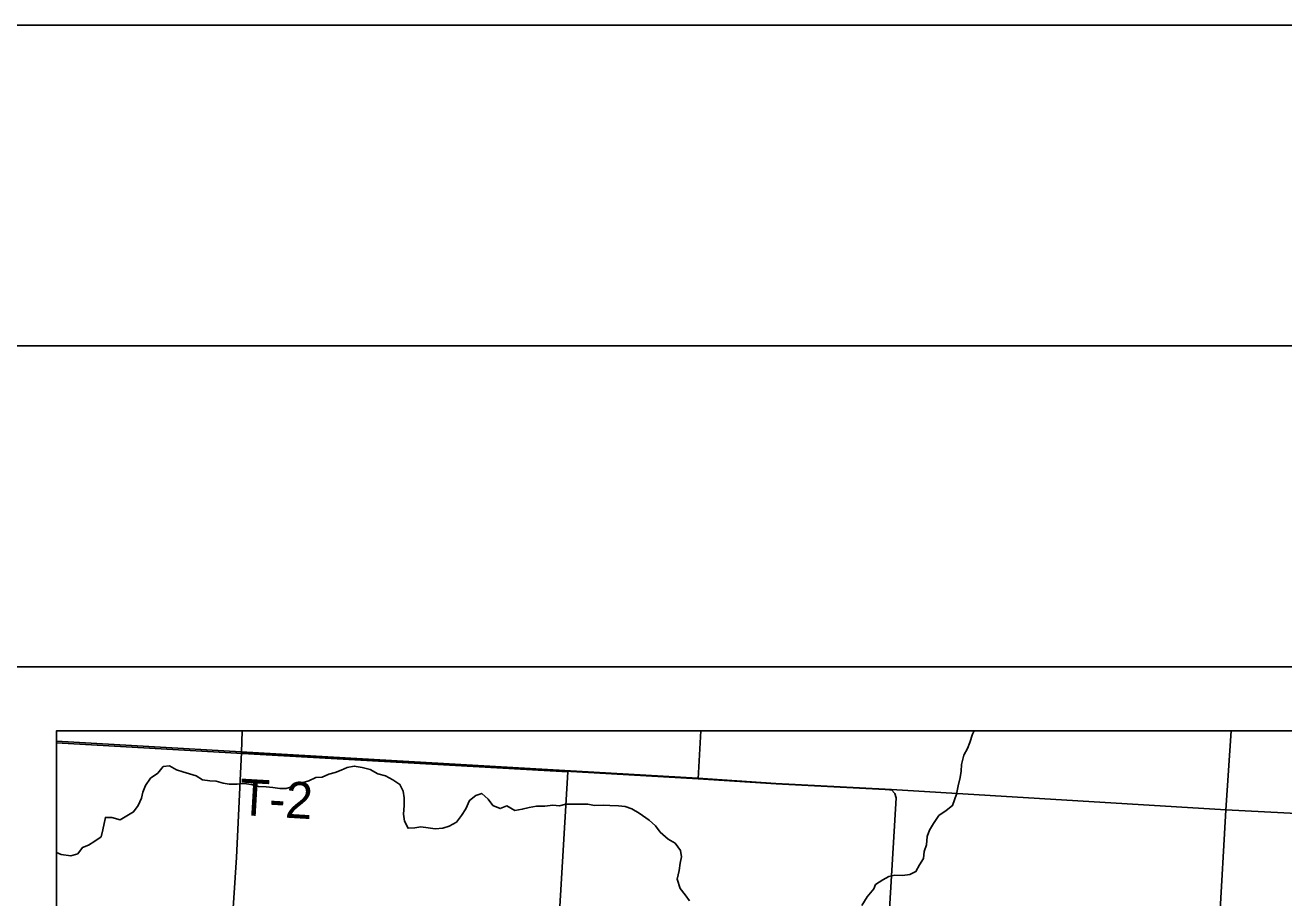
# Model space of a CAD drawing. Extents: x 0 to 91.3, y -0.7 to 22.
# Drawn here: x 2.051 to 4.012, y 20.64 to 22 of the extents above; entities that cross this region are included whole.
import ezdxf

# ---------------------------------------------------------------- set-up
doc = ezdxf.new("R2010")
doc.units = 0
for name, color, linetype in [('GM_X_Corporation', 7, 'Continuous'), ('GM_X_County_Road', 7, 'Continuous'), ('GM_X_Minor_River', 7, 'Continuous'), ('GM_X_State_Route', 7, 'Continuous'), ('GM_X_Township_Road', 7, 'Continuous'), ('GM_X_Township_Road_Text', 7, 'Continuous'), ('SH_Border', 7, 'Continuous'), ('SH_Cut_Line', 7, 'Continuous'), ('SH_Data', 7, 'Continuous')]:
    doc.layers.add(name, color=color, linetype=linetype)

msp = doc.modelspace()

# ---------------------------------------------------------------- linework, layer by layer
at = {"layer": 'GM_X_Corporation'}
for points in [[(4.9555, 20.9), (2.1, 20.9), (2.1, 20.8844), (2.3878, 20.8673), (3.0994, 20.8263), (3.2209, 20.8181), (3.3908, 20.8093), (3.4006, 20.8086), (3.9216, 20.777), (4.9448, 20.7239)], [(4.9555, 20.9), (2.1, 20.9), (2.1, 20.8844), (2.3878, 20.8673), (3.0994, 20.8263), (3.2209, 20.8181), (3.3908, 20.8093), (3.4006, 20.8086), (3.9216, 20.777), (4.9448, 20.7239)], [(2.1, 20.8816), (2.1, 19.8366), (2.8346, 19.7864), (2.8964, 20.8363), (2.3899, 20.8648)]]:
    msp.add_lwpolyline(points, close=True, dxfattribs=at)
for points in [[(4.7833, 18.1361), (4.8242, 18.6326), (4.8251, 18.6439), (4.8263, 18.646), (4.8271, 18.6491), (4.8277, 18.656), (4.8336, 18.7529), (4.834, 18.7568), (4.8352, 18.7619), (4.9205, 20.3667), (4.9376, 20.6305), (4.9448, 20.7239), (3.9216, 20.777), (3.4006, 20.8086), (3.3908, 20.8093), (3.2209, 20.8181), (3.0994, 20.8263), (2.3878, 20.8673), (2.1, 20.8844), (2.1, 14.1)], [(4.7833, 18.1361), (4.8242, 18.6326), (4.8251, 18.6439), (4.8263, 18.646), (4.8271, 18.6491), (4.8277, 18.656), (4.8336, 18.7529), (4.834, 18.7568), (4.8352, 18.7619), (4.9205, 20.3667), (4.9376, 20.6305), (4.9448, 20.7239), (3.9216, 20.777), (3.4006, 20.8086), (3.3908, 20.8093), (3.2209, 20.8181), (3.0994, 20.8263), (2.3878, 20.8673), (2.1, 20.8844), (2.1, 15.7138)]]:
    msp.add_lwpolyline(points, dxfattribs=at)
at = {"layer": 'GM_X_County_Road'}
msp.add_lwpolyline([(3.8606, 19.7255), (3.8807, 20.1515), (3.9073, 20.5159), (3.9118, 20.603), (3.9219, 20.7764)], dxfattribs=at)
at = {"layer": 'GM_X_Minor_River'}
for points in [[(3.502, 20.8014), (3.5048, 20.8146), (3.5078, 20.8275), (3.5093, 20.8374), (3.51, 20.848), (3.5133, 20.8621), (3.5193, 20.8727), (3.5231, 20.8822), (3.5272, 20.8952), (3.5297, 20.9)], [(2.1, 20.7104), (2.1072, 20.7075), (2.1223, 20.7054), (2.1333, 20.7084), (2.1406, 20.7182), (2.1501, 20.7222), (2.16, 20.7282), (2.1695, 20.7353), (2.1723, 20.746), (2.1742, 20.7558), (2.1762, 20.7653), (2.1861, 20.7652), (2.1993, 20.7613), (2.2099, 20.768), (2.2202, 20.774), (2.2271, 20.7838), (2.2325, 20.7951), (2.2345, 20.8046), (2.2387, 20.8152), (2.2468, 20.8265), (2.2578, 20.8343), (2.2663, 20.8449), (2.2761, 20.8456), (2.287, 20.8397), (2.2968, 20.8366), (2.3074, 20.8331), (2.3179, 20.8299), (2.3277, 20.8241), (2.3391, 20.8221), (2.3489, 20.822), (2.3595, 20.8189), (2.3693, 20.8172), (2.3818, 20.8171), (2.3924, 20.8181), (2.4033, 20.8165), (2.415, 20.8137), (2.4267, 20.8129), (2.4373, 20.812), (2.4479, 20.8104), (2.4577, 20.8103), (2.4703, 20.8139), (2.4805, 20.8188), (2.493, 20.8221), (2.5041, 20.8273), (2.5139, 20.8279), (2.5245, 20.8327), (2.534, 20.8353), (2.5435, 20.839), (2.553, 20.8431), (2.564, 20.8453), (2.5761, 20.8429), (2.5886, 20.8401), (2.6006, 20.8331), (2.6127, 20.8303), (2.624, 20.8237), (2.6352, 20.8168), (2.6401, 20.8061), (2.6419, 20.7958), (2.6418, 20.7837), (2.6405, 20.7704), (2.6423, 20.7594), (2.6479, 20.7483), (2.6585, 20.7489), (2.6679, 20.7504), (2.6789, 20.7491), (2.6902, 20.7475), (2.702, 20.7485), (2.7118, 20.7518), (2.7232, 20.7578), (2.7309, 20.7683), (2.7378, 20.7785), (2.7436, 20.7918), (2.7531, 20.7996), (2.7626, 20.8026), (2.7728, 20.7937), (2.7799, 20.7838), (2.7915, 20.7791), (2.8018, 20.7836), (2.8142, 20.7762), (2.8256, 20.778), (2.8366, 20.7809), (2.8476, 20.7827), (2.8608, 20.783), (2.8733, 20.7844), (2.8839, 20.7835), (2.8934, 20.7857), (2.9059, 20.7859), (2.9157, 20.7862)], [(2.9157, 20.7862), (2.9278, 20.7857), (2.9384, 20.7837), (2.9516, 20.7843), (2.9622, 20.7838), (2.9755, 20.7833), (2.986, 20.7821), (2.9966, 20.7789), (3.0079, 20.772), (3.0233, 20.7608), (3.0334, 20.752), (3.0405, 20.7424), (3.0529, 20.7316), (3.0638, 20.7251), (3.0721, 20.714), (3.0739, 20.7037), (3.0719, 20.6942), (3.0699, 20.6824), (3.0671, 20.6692), (3.0714, 20.6544)], [(3.502, 20.8014), (3.4961, 20.7838), (3.4858, 20.7763), (3.4748, 20.7684), (3.4663, 20.7559), (3.4598, 20.7454), (3.4563, 20.7355), (3.4554, 20.7226), (3.4519, 20.7124), (3.4507, 20.7014), (3.4446, 20.6916), (3.4388, 20.681), (3.4293, 20.6762), (3.4179, 20.6747), (3.4062, 20.6752), (3.3967, 20.6731), (3.3872, 20.6678), (3.3758, 20.6607), (3.3735, 20.6541)], [(3.5018, 20.8008), (3.5018, 20.8009)], [(3.0714, 20.6544), (3.0793, 20.6448), (3.0861, 20.6353)], [(3.3544, 20.628), (3.3632, 20.6413), (3.3735, 20.6541)]]:
    msp.add_lwpolyline(points, dxfattribs=at)
at = {"layer": 'GM_X_State_Route'}
msp.add_line((2.3881, 20.8667), (2.3891, 20.9), dxfattribs=at)
msp.add_lwpolyline([(2.3236, 19.8526), (2.354, 20.2835), (2.3719, 20.5693), (2.3803, 20.7028), (2.3881, 20.8667)], dxfattribs=at)
at = {"layer": 'GM_X_Township_Road'}
for p, q in [((3.0997, 20.8257), (3.104, 20.9)), ((3.9219, 20.7764), (3.93, 20.9))]:
    msp.add_line(p, q, dxfattribs=at)
for points in [[(2.3881, 20.8667), (3.0997, 20.8257), (3.2212, 20.8176), (3.391, 20.8088), (3.3975, 20.8083), (3.4008, 20.8081)], [(3.3467, 19.7553), (3.3647, 20.0567), (3.3715, 20.1817), (3.377, 20.2742), (3.4081, 20.7959), (3.4063, 20.8026), (3.4008, 20.8081)]]:
    msp.add_lwpolyline(points, dxfattribs=at)
at = {"layer": 'SH_Border'}
msp.add_lwpolyline([(1.5, 21.5), (33.5, 21.5), (33.5, 0.5), (1.5, 0.5)], close=True, dxfattribs=at)
at = {"layer": 'SH_Cut_Line'}
msp.add_lwpolyline([(0, 0), (34, 0), (34, 22), (0, 22)], close=True, dxfattribs=at)
at = {"layer": 'SH_Data'}
for p, q in [((2, 21), (9, 21)), ((2.1, 20.9), (2.1, 14.1)), ((2.1, 20.9), (8.9, 20.9))]:
    msp.add_line(p, q, dxfattribs=at)

# ---------------------------------------------------------------- texts
at = {"layer": 'GM_X_Township_Road_Text'}
msp.add_text('T-2', height=0.05682, rotation=356.6615, dxfattribs=at).set_placement((2.3838, 20.7692))

doc.saveas('drawing.dxf')
